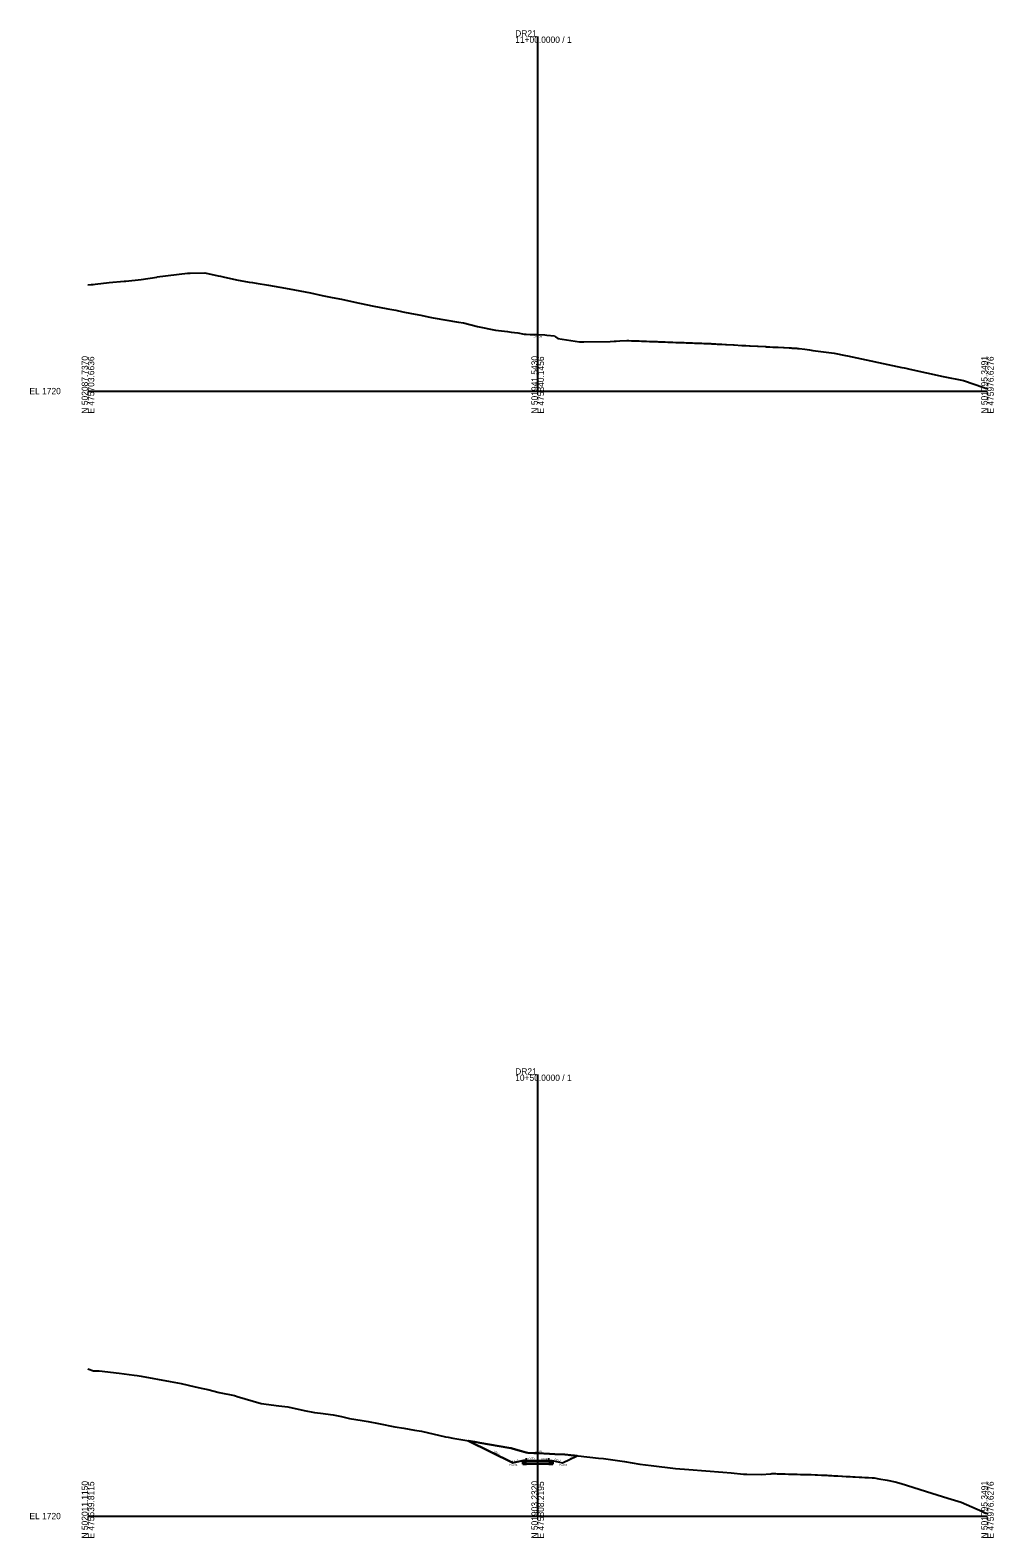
# Model space of a CAD drawing. Extents: x 78347 to 78775, y -92484 to -91314.
# Drawn here: x 78347 to 78775, y -91984 to -91314 of the extents above; entities that cross this region are included whole.
import ezdxf

# ---------------------------------------------------------------- set-up
doc = ezdxf.new("R2010")
doc.units = 0
for name, color, linetype in [('Exist Cross Section Cell', 7, 'Continuous'), ('Exist XS Center Line Elevation Label', 7, 'Continuous'), ('Exist XS Ground Line', 7, 'Continuous'), ('Prop CMT Shallow Undercut Boundary', 7, 'Continuous'), ('Prop XS Ditch Slope Text', 7, 'Continuous'), ('Prop XS Ditch Standard Text', 7, 'Continuous'), ('Prop XS Earthwork Shape', 7, 'Continuous'), ('Prop XS EOT Tick Mark', 7, 'Continuous'), ('Prop XS Finish Grade', 7, 'Continuous'), ('Prop XS Finish Grade Earthwork', 7, 'Continuous'), ('Prop XS Finish Grade Pavement', 7, 'Continuous'), ('Prop XS Pvmt Edge Slope', 7, 'Continuous'), ('Prop XS SE Text', 7, 'Continuous'), ('Prop XS Shoulder Borrow Shape', 7, 'Continuous'), ('Prop XS Side Slope Text', 7, 'Continuous'), ('Prop XS Subgrade Earthwork', 7, 'Continuous')]:
    doc.layers.add(name, color=color, linetype=linetype)

msp = doc.modelspace()

# ---------------------------------------------------------------- linework, layer by layer
at = {"layer": 'Exist Cross Section Cell'}
for p, q in [((78572.41, -91474.1), (78572.41, -91316.53)), ((78372.41, -91474.1), (78572.41, -91474.1)), ((78572.41, -91474.1), (78772.41, -91474.1)), ((78572.41, -91974.1), (78572.41, -91777.89)), ((78372.41, -91974.1), (78572.41, -91974.1)), ((78572.41, -91974.1), (78772.41, -91974.1))]:
    msp.add_line(p, q, dxfattribs=at)
at = {"layer": 'Exist XS Ground Line'}
for p, q in [((78403.22, -91423.4), (78416.68, -91421.76)), ((78416.68, -91421.76), (78417.88, -91421.69)), ((78417.88, -91421.69), (78424.34, -91421.58)), ((78424.34, -91421.58), (78430.36, -91422.82)), ((78372.41, -91426.92), (78373.91, -91426.8)), ((78373.91, -91426.8), (78374.8, -91426.7)), ((78374.8, -91426.7), (78375.63, -91426.63)), ((78375.63, -91426.63), (78381.88, -91425.91)), ((78381.88, -91425.91), (78388.57, -91425.31)), ((78388.57, -91425.31), (78388.95, -91425.27)), ((78388.95, -91425.27), (78389.31, -91425.24)), ((78389.31, -91425.24), (78396.03, -91424.51)), ((78396.03, -91424.51), (78403, -91423.43)), ((78403, -91423.43), (78403.11, -91423.42)), ((78403.11, -91423.42), (78403.22, -91423.4)), ((78430.36, -91422.82), (78431.41, -91423.05)), ((78431.41, -91423.05), (78432.54, -91423.37)), ((78432.54, -91423.37), (78438.49, -91424.63)), ((78438.49, -91424.63), (78444.05, -91425.63)), ((78444.05, -91425.63), (78445.57, -91425.84)), ((78445.57, -91425.84), (78447.19, -91426.17)), ((78447.19, -91426.17), (78452.64, -91427.09)), ((78452.64, -91427.09), (78457.73, -91427.99)), ((78457.73, -91427.99), (78461.85, -91428.64)), ((78461.85, -91428.64), (78471.41, -91430.51)), ((78471.41, -91430.51), (78476.51, -91431.61)), ((78476.51, -91431.61), (78480.95, -91432.5)), ((78480.95, -91432.5), (78485.1, -91433.29)), ((78485.1, -91433.29), (78491.16, -91434.56)), ((78491.16, -91434.56), (78498.78, -91436.17)), ((78498.78, -91436.17), (78505.82, -91437.53)), ((78505.82, -91437.53), (78509.26, -91438.16)), ((78509.26, -91438.16), (78512.46, -91438.85)), ((78512.46, -91438.85), (78516.33, -91439.63)), ((78516.33, -91439.63), (78520.48, -91440.35)), ((78520.48, -91440.35), (78523.69, -91441.05)), ((78523.69, -91441.05), (78525.96, -91441.55)), ((78525.96, -91441.55), (78537.24, -91443.41)), ((78537.24, -91443.41), (78539.41, -91443.8)), ((78539.41, -91443.8), (78545.69, -91445.33)), ((78545.69, -91445.33), (78553.66, -91447.02)), ((78553.66, -91447.02), (78558.92, -91447.64)), ((78558.92, -91447.64), (78560.54, -91447.86)), ((78560.54, -91447.86), (78563.5, -91448.28)), ((78563.5, -91448.28), (78566.37, -91448.82)), ((78566.37, -91448.82), (78566.64, -91448.76)), ((78566.64, -91448.76), (78566.8, -91448.78)), ((78566.8, -91448.78), (78567.32, -91448.85)), ((78567.32, -91448.85), (78568.99, -91448.91)), ((78568.99, -91448.91), (78572.41, -91449.02)), ((78572.41, -91449.02), (78575.54, -91449.12)), ((78575.54, -91449.12), (78576.44, -91449.22)), ((78576.44, -91449.22), (78579.9, -91449.58)), ((78579.9, -91449.58), (78580.37, -91450.01)), ((78580.37, -91450.01), (78581.38, -91450.71)), ((78581.38, -91450.71), (78591.04, -91452.17)), ((78591.04, -91452.17), (78592.93, -91452.21)), ((78592.93, -91452.21), (78604.58, -91452.07)), ((78604.58, -91452.07), (78606.48, -91451.97)), ((78606.48, -91451.97), (78607.3, -91451.92)), ((78607.3, -91451.92), (78608.93, -91451.82)), ((78608.93, -91451.82), (78611.98, -91451.64)), ((78611.98, -91451.64), (78612.55, -91451.66)), ((78612.55, -91451.66), (78612.93, -91451.67)), ((78612.93, -91451.67), (78614.13, -91451.72)), ((78614.13, -91451.72), (78614.79, -91451.74)), ((78614.79, -91451.74), (78615.57, -91451.77)), ((78615.57, -91451.77), (78615.61, -91451.77)), ((78615.61, -91451.77), (78615.86, -91451.78)), ((78615.86, -91451.78), (78616.14, -91451.79)), ((78616.14, -91451.79), (78617.49, -91451.84)), ((78617.49, -91451.84), (78618.55, -91451.89)), ((78618.55, -91451.89), (78619.11, -91451.91)), ((78619.11, -91451.91), (78619.22, -91451.91)), ((78619.22, -91451.91), (78620.74, -91451.96)), ((78620.74, -91451.96), (78622.19, -91452.02)), ((78622.19, -91452.02), (78622.5, -91452.03)), ((78622.5, -91452.03), (78622.92, -91452.05)), ((78622.92, -91452.05), (78625.58, -91452.14)), ((78625.58, -91452.14), (78626.06, -91452.16)), ((78626.06, -91452.16), (78626.57, -91452.18)), ((78626.57, -91452.18), (78627.84, -91452.23)), ((78627.84, -91452.23), (78629.02, -91452.27)), ((78629.02, -91452.27), (78630.23, -91452.31)), ((78630.23, -91452.31), (78631.36, -91452.35)), ((78631.36, -91452.35), (78632.43, -91452.39)), ((78632.43, -91452.39), (78633.89, -91452.45)), ((78633.89, -91452.45), (78635.84, -91452.52)), ((78635.84, -91452.52), (78636.66, -91452.55)), ((78636.66, -91452.55), (78637.56, -91452.58)), ((78637.56, -91452.58), (78638.46, -91452.61)), ((78638.46, -91452.61), (78639.29, -91452.65)), ((78639.29, -91452.65), (78641.23, -91452.72)), ((78641.23, -91452.72), (78642.14, -91452.76)), ((78642.14, -91452.76), (78642.69, -91452.77)), ((78642.69, -91452.77), (78643.75, -91452.8)), ((78643.75, -91452.8), (78644.88, -91452.84)), ((78644.88, -91452.84), (78645.38, -91452.86)), ((78645.38, -91452.86), (78646.32, -91452.9)), ((78646.32, -91452.9), (78647.23, -91452.94)), ((78647.23, -91452.94), (78648.29, -91452.97)), ((78648.29, -91452.97), (78649.16, -91453.01)), ((78649.16, -91453.01), (78649.31, -91453.02)), ((78649.31, -91453.02), (78649.52, -91453.03)), ((78649.52, -91453.03), (78649.67, -91453.04)), ((78649.67, -91453.04), (78651.44, -91453.15)), ((78651.44, -91453.15), (78652.17, -91453.19)), ((78652.17, -91453.19), (78652.95, -91453.24)), ((78652.95, -91453.24), (78654.28, -91453.31)), ((78654.28, -91453.31), (78655.87, -91453.4)), ((78655.87, -91453.4), (78656.39, -91453.43)), ((78656.39, -91453.43), (78659.5, -91453.6)), ((78659.5, -91453.6), (78659.67, -91453.61)), ((78659.67, -91453.61), (78659.82, -91453.62)), ((78659.82, -91453.62), (78663.13, -91453.79)), ((78663.13, -91453.79), (78663.21, -91453.8)), ((78663.21, -91453.8), (78664.97, -91453.9)), ((78664.97, -91453.9), (78666.66, -91453.98)), ((78666.66, -91453.98), (78666.86, -91453.99)), ((78666.86, -91453.99), (78670.08, -91454.16)), ((78670.08, -91454.16), (78670.28, -91454.17)), ((78670.28, -91454.17), (78670.5, -91454.18)), ((78670.5, -91454.18), (78673.48, -91454.34)), ((78673.48, -91454.34), (78673.79, -91454.36)), ((78673.79, -91454.36), (78674.14, -91454.38)), ((78674.14, -91454.38), (78675.59, -91454.45)), ((78675.59, -91454.45), (78676.91, -91454.52)), ((78676.91, -91454.52), (78677.84, -91454.57)), ((78677.84, -91454.57), (78679.33, -91454.65)), ((78679.33, -91454.65), (78681.65, -91454.77)), ((78681.65, -91454.77), (78681.72, -91454.77)), ((78681.72, -91454.77), (78681.82, -91454.78)), ((78681.82, -91454.78), (78682.01, -91454.79)), ((78682.01, -91454.79), (78684.28, -91454.91)), ((78684.28, -91454.91), (78685.06, -91454.95)), ((78685.06, -91454.95), (78685.51, -91454.98)), ((78685.51, -91454.98), (78687.76, -91455.1)), ((78687.76, -91455.1), (78687.9, -91455.11)), ((78687.9, -91455.11), (78688.11, -91455.12)), ((78688.11, -91455.12), (78688.3, -91455.13)), ((78688.3, -91455.13), (78688.62, -91455.15)), ((78688.62, -91455.15), (78691.21, -91455.51)), ((78691.21, -91455.51), (78693.31, -91455.8)), ((78693.31, -91455.8), (78694.78, -91456.01)), ((78694.78, -91456.01), (78704.21, -91457.28)), ((78704.21, -91457.28), (78709.25, -91458.22)), ((78709.25, -91458.22), (78710.21, -91458.48)), ((78710.21, -91458.48), (78734.32, -91463.58)), ((78734.32, -91463.58), (78735.36, -91463.77)), ((78735.36, -91463.77), (78736.17, -91463.92)), ((78736.17, -91463.92), (78737.91, -91464.37)), ((78737.91, -91464.37), (78752.64, -91467.59)), ((78752.64, -91467.59), (78761.73, -91469.41)), ((78761.73, -91469.41), (78770.81, -91472.5)), ((78770.81, -91472.5), (78771.56, -91472.79)), ((78771.56, -91472.79), (78772.41, -91472.82)), ((78372.41, -91908.7), (78374.93, -91909.5)), ((78374.93, -91909.5), (78377.38, -91909.62)), ((78377.38, -91909.62), (78386.26, -91910.59)), ((78386.26, -91910.59), (78392.96, -91911.51)), ((78392.96, -91911.51), (78394.32, -91911.61)), ((78394.32, -91911.61), (78396.14, -91911.94)), ((78396.14, -91911.94), (78409.05, -91914.27)), ((78409.05, -91914.27), (78413.82, -91915.26)), ((78413.82, -91915.26), (78420.15, -91916.61)), ((78420.15, -91916.61), (78423.53, -91917.39)), ((78423.53, -91917.39), (78425.7, -91917.88)), ((78425.7, -91917.88), (78430.77, -91919.22)), ((78430.77, -91919.22), (78437.58, -91920.58)), ((78437.58, -91920.58), (78438.01, -91920.7)), ((78438.01, -91920.7), (78438.7, -91920.91)), ((78438.7, -91920.91), (78449.45, -91924.14)), ((78449.45, -91924.14), (78457.24, -91925.08)), ((78457.24, -91925.08), (78461.33, -91925.63)), ((78461.33, -91925.63), (78468.63, -91927.12)), ((78468.63, -91927.12), (78473.21, -91928.01)), ((78473.21, -91928.01), (78475.78, -91928.41)), ((78475.78, -91928.41), (78481.45, -91929.06)), ((78481.45, -91929.06), (78485.09, -91929.85)), ((78485.09, -91929.85), (78488.69, -91930.73)), ((78488.69, -91930.73), (78494.32, -91931.61)), ((78494.32, -91931.61), (78496.97, -91932.08)), ((78496.97, -91932.08), (78501.68, -91932.95)), ((78501.68, -91932.95), (78508.84, -91934.38)), ((78508.84, -91934.38), (78512.86, -91935.11)), ((78512.86, -91935.11), (78517.65, -91935.95)), ((78517.65, -91935.95), (78520.72, -91936.43)), ((78520.72, -91936.43), (78531.41, -91938.83)), ((78531.41, -91938.83), (78532.6, -91939.09)), ((78532.6, -91939.09), (78534.73, -91939.46)), ((78534.73, -91939.46), (78544.48, -91941.16)), ((78544.48, -91941.16), (78546.61, -91941.55)), ((78546.61, -91941.55), (78559.59, -91943.78)), ((78559.59, -91943.78), (78560.67, -91943.98)), ((78560.67, -91943.98), (78561.57, -91944.23)), ((78561.57, -91944.23), (78565.26, -91945.27)), ((78565.26, -91945.27), (78567.3, -91945.8)), ((78567.3, -91945.8), (78567.96, -91946)), ((78567.96, -91946), (78570.73, -91946.12)), ((78570.73, -91946.12), (78572.41, -91946.2)), ((78572.41, -91946.2), (78577.72, -91946.44)), ((78577.72, -91946.44), (78580.01, -91946.55)), ((78580.01, -91946.55), (78584.53, -91946.76)), ((78584.53, -91946.76), (78590.34, -91947.31)), ((78590.34, -91947.31), (78599.44, -91948.33)), ((78599.44, -91948.33), (78601.68, -91948.57)), ((78601.68, -91948.57), (78610.98, -91949.92)), ((78610.98, -91949.92), (78617.81, -91951.02)), ((78617.81, -91951.02), (78622.93, -91951.57)), ((78622.93, -91951.57), (78633.69, -91952.95)), ((78633.69, -91952.95), (78639.65, -91953.44)), ((78639.65, -91953.44), (78654.72, -91954.53)), ((78654.72, -91954.53), (78658.43, -91954.96)), ((78658.43, -91954.96), (78663.92, -91955.42)), ((78663.92, -91955.42), (78664.9, -91955.52)), ((78664.9, -91955.52), (78665.33, -91955.51)), ((78665.33, -91955.51), (78671.72, -91955.7)), ((78671.72, -91955.7), (78676, -91955.31)), ((78676, -91955.31), (78676.5, -91955.22)), ((78676.5, -91955.22), (78677.12, -91955.23)), ((78677.12, -91955.23), (78678.13, -91955.25)), ((78678.13, -91955.25), (78678.89, -91955.27)), ((78678.89, -91955.27), (78678.92, -91955.27)), ((78678.92, -91955.27), (78679.23, -91955.28)), ((78679.23, -91955.28), (78679.75, -91955.3)), ((78679.75, -91955.3), (78680.8, -91955.33)), ((78680.8, -91955.33), (78680.94, -91955.34)), ((78680.94, -91955.34), (78682.44, -91955.38)), ((78682.44, -91955.38), (78683.89, -91955.42)), ((78683.89, -91955.42), (78684.69, -91955.44)), ((78684.69, -91955.44), (78686.01, -91955.48)), ((78686.01, -91955.48), (78686.87, -91955.5)), ((78686.87, -91955.5), (78687.84, -91955.53)), ((78687.84, -91955.53), (78689.33, -91955.57)), ((78689.33, -91955.57), (78689.86, -91955.58)), ((78689.86, -91955.58), (78691.44, -91955.63)), ((78691.44, -91955.63), (78692.81, -91955.68)), ((78692.81, -91955.68), (78693.26, -91955.69)), ((78693.26, -91955.69), (78693.96, -91955.71)), ((78693.96, -91955.71), (78695.78, -91955.76)), ((78695.78, -91955.76), (78696.75, -91955.8)), ((78696.75, -91955.8), (78698.56, -91955.86)), ((78698.56, -91955.86), (78698.74, -91955.87)), ((78698.74, -91955.87), (78699.29, -91955.9)), ((78699.29, -91955.9), (78700.92, -91955.99)), ((78700.92, -91955.99), (78701.69, -91956.03)), ((78701.69, -91956.03), (78703.24, -91956.12)), ((78703.24, -91956.12), (78704.09, -91956.16)), ((78704.09, -91956.16), (78704.64, -91956.19)), ((78704.64, -91956.19), (78705.93, -91956.26)), ((78705.93, -91956.26), (78707.64, -91956.35)), ((78707.64, -91956.35), (78707.88, -91956.37)), ((78707.88, -91956.37), (78709.51, -91956.46)), ((78709.51, -91956.46), (78710.59, -91956.51)), ((78710.59, -91956.51), (78711.36, -91956.56)), ((78711.36, -91956.56), (78712.55, -91956.62)), ((78712.55, -91956.62), (78713.57, -91956.68)), ((78713.57, -91956.68), (78715.31, -91956.77)), ((78715.31, -91956.77), (78716.6, -91956.85)), ((78716.6, -91956.85), (78717.84, -91956.91)), ((78717.84, -91956.91), (78718.03, -91956.92)), ((78718.03, -91956.92), (78718.1, -91956.93)), ((78718.1, -91956.93), (78718.12, -91956.93)), ((78718.12, -91956.93), (78719.5, -91957.01)), ((78719.5, -91957.01), (78721.1, -91957.1)), ((78721.1, -91957.1), (78721.8, -91957.13)), ((78721.8, -91957.13), (78722.07, -91957.16)), ((78722.07, -91957.16), (78724.09, -91957.52)), ((78724.09, -91957.52), (78727.81, -91958.2)), ((78727.81, -91958.2), (78731.36, -91958.84)), ((78731.36, -91958.84), (78734.03, -91959.68)), ((78734.03, -91959.68), (78747.61, -91963.92)), ((78747.61, -91963.92), (78754.71, -91966.2)), ((78754.71, -91966.2), (78760.64, -91968)), ((78760.64, -91968), (78770.12, -91972.07)), ((78770.12, -91972.07), (78771.7, -91972.8)), ((78771.7, -91972.8), (78772.41, -91972.82))]:
    msp.add_line(p, q, dxfattribs=at)
at = {"layer": 'Prop CMT Shallow Undercut Boundary'}
for p, q in [((78565.73, -91950.05), (78567.41, -91950.02)), ((78566.73, -91950.03), (78565.73, -91950.05)), ((78565.73, -91951.05), (78565.73, -91950.05)), ((78565.73, -91950.05), (78565.73, -91951.05)), ((78567.41, -91951.02), (78565.73, -91951.05)), ((78565.73, -91951.05), (78567.41, -91951.02)), ((78567.41, -91950.02), (78566.73, -91950.03)), ((78567.41, -91950.02), (78572.41, -91949.92)), ((78572.41, -91949.92), (78567.41, -91950.02)), ((78572.41, -91950.92), (78567.41, -91951.02)), ((78567.41, -91951.02), (78572.41, -91950.92)), ((78572.41, -91949.92), (78577.4, -91950.02)), ((78577.4, -91950.02), (78572.41, -91949.92)), ((78577.4, -91951.02), (78572.41, -91950.92)), ((78572.41, -91950.92), (78577.4, -91951.02)), ((78577.4, -91950.02), (78579.08, -91950.05)), ((78578.08, -91950.03), (78577.4, -91950.02)), ((78579.08, -91951.05), (78577.4, -91951.02)), ((78577.4, -91951.02), (78579.08, -91951.05)), ((78579.08, -91950.05), (78578.08, -91950.03)), ((78579.08, -91950.05), (78579.08, -91951.05)), ((78579.08, -91951.05), (78579.08, -91950.05))]:
    msp.add_line(p, q, dxfattribs=at)
at = {"layer": 'Prop XS Earthwork Shape'}
msp.add_lwpolyline([(78578.08, -91950.03), (78578.67, -91949.45), (78579.41, -91949.51), (78583.44, -91950.51), (78589.97, -91947.27), (78584.53, -91946.76), (78580.01, -91946.55), (78577.72, -91946.44), (78572.41, -91946.2), (78570.73, -91946.12), (78567.96, -91946), (78567.3, -91945.8), (78565.26, -91945.27), (78561.57, -91944.23), (78560.67, -91943.98), (78559.59, -91943.78), (78546.61, -91941.55), (78544.48, -91941.16), (78541.51, -91940.64), (78561.38, -91950.51), (78565.4, -91949.51), (78566.15, -91949.45), (78566.73, -91950.03), (78567.41, -91950.02), (78572.41, -91949.92), (78577.4, -91950.02)], close=True, dxfattribs=at)
at = {"layer": 'Prop XS EOT Tick Mark'}
for p, q in [((78567.41, -91949.35), (78567.41, -91948.35)), ((78577.4, -91949.35), (78577.4, -91948.35))]:
    msp.add_line(p, q, dxfattribs=at)
at = {"layer": 'Prop XS Finish Grade'}
for p, q in [((78567.41, -91949.35), (78566.15, -91949.45)), ((78577.4, -91949.35), (78578.67, -91949.45))]:
    msp.add_line(p, q, dxfattribs=at)
at = {"layer": 'Prop XS Finish Grade Earthwork'}
for p, q in [((78561.38, -91950.51), (78541.51, -91940.64)), ((78565.4, -91949.51), (78561.38, -91950.51)), ((78566.15, -91949.45), (78565.4, -91949.51)), ((78578.67, -91949.45), (78579.41, -91949.51)), ((78579.41, -91949.51), (78583.44, -91950.51)), ((78583.44, -91950.51), (78589.97, -91947.27))]:
    msp.add_line(p, q, dxfattribs=at)
at = {"layer": 'Prop XS Finish Grade Pavement'}
for p, q in [((78567.41, -91949.35), (78572.41, -91949.25)), ((78572.41, -91949.25), (78577.4, -91949.35))]:
    msp.add_line(p, q, dxfattribs=at)
at = {"layer": 'Prop XS Pvmt Edge Slope'}
for p, q in [((78567.41, -91949.35), (78566.73, -91950.03)), ((78577.4, -91949.35), (78578.08, -91950.03))]:
    msp.add_line(p, q, dxfattribs=at)
at = {"layer": 'Prop XS Shoulder Borrow Shape'}
for points in [[(78567.41, -91949.35), (78566.15, -91949.45), (78566.73, -91950.03)], [(78577.4, -91949.35), (78578.67, -91949.45), (78578.08, -91950.03)]]:
    msp.add_lwpolyline(points, close=True, dxfattribs=at)
at = {"layer": 'Prop XS Subgrade Earthwork'}
for p, q in [((78566.73, -91950.03), (78566.15, -91949.45)), ((78567.41, -91950.02), (78566.73, -91950.03)), ((78572.41, -91949.92), (78567.41, -91950.02)), ((78577.4, -91950.02), (78572.41, -91949.92)), ((78577.4, -91950.02), (78578.08, -91950.03)), ((78578.08, -91950.03), (78578.67, -91949.45))]:
    msp.add_line(p, q, dxfattribs=at)

# ---------------------------------------------------------------- texts
at = {"layer": 'Exist Cross Section Cell'}
for s, p in [('DR21', (78562.41, -91316.53)), ('11+00.0000 / 1', (78562.41, -91319.33)), ('EL 1720', (78346.41, -91475.5)), ('DR21', (78562.41, -91777.89)), ('10+50.0000 / 1', (78562.41, -91780.69)), ('EL 1720', (78346.41, -91975.5))]:
    msp.add_text(s, height=2.8, dxfattribs=at).set_placement(p)
for s, p in [('N 502087.7370', (78372.41, -91484.1)), ('E 475703.6636', (78375.21, -91484.1)), ('N 501941.5430', (78572.41, -91484.1)), ('E 475840.1456', (78575.21, -91484.1)), ('N 501795.3491', (78772.41, -91484.1)), ('E 475976.6276', (78775.21, -91484.1)), ('N 502011.1150', (78372.41, -91984.1)), ('E 475639.8115', (78375.21, -91984.1)), ('N 501903.2320', (78572.41, -91984.1)), ('E 475808.2195', (78575.21, -91984.1)), ('N 501795.3491', (78772.41, -91984.1)), ('E 475976.6276', (78775.21, -91984.1))]:
    msp.add_text(s, height=2.8, rotation=90, dxfattribs=at).set_placement(p)
at = {"layer": 'Exist XS Center Line Elevation Label'}
for s, p in [('1745.08', (78570.58, -91450.21)), ('1747.90', (78570.47, -91945.73))]:
    msp.add_text(s, height=0.75, dxfattribs=at).set_placement(p)
at = {"layer": 'Prop XS Ditch Slope Text'}
for rotation, p in [(13.94961, (78561.07, -91950.28)), (346.05916, (78579.78, -91949.15))]:
    msp.add_text('4.03:1', height=0.75, rotation=rotation, dxfattribs=at).set_placement(p)
at = {"layer": 'Prop XS Ditch Standard Text'}
for p in [(78559.57, -91951.73), (78581.63, -91951.73)]:
    msp.add_text('1744.04', height=0.75, dxfattribs=at).set_placement(p)
at = {"layer": 'Prop XS SE Text'}
for rotation, p in [(1.14576, (78568.37, -91948.96)), (358.85424, (78574.01, -91949))]:
    msp.add_text('0.020', height=0.75, rotation=rotation, dxfattribs=at).set_placement(p)
at = {"layer": 'Prop XS Side Slope Text'}
for rotation, p in [(333.58236, (78552.81, -91945.68)), (26.4027, (78586.77, -91948.55))]:
    msp.add_text('2.01:1', height=0.75, rotation=rotation, dxfattribs=at).set_placement(p)

doc.saveas('drawing.dxf')
